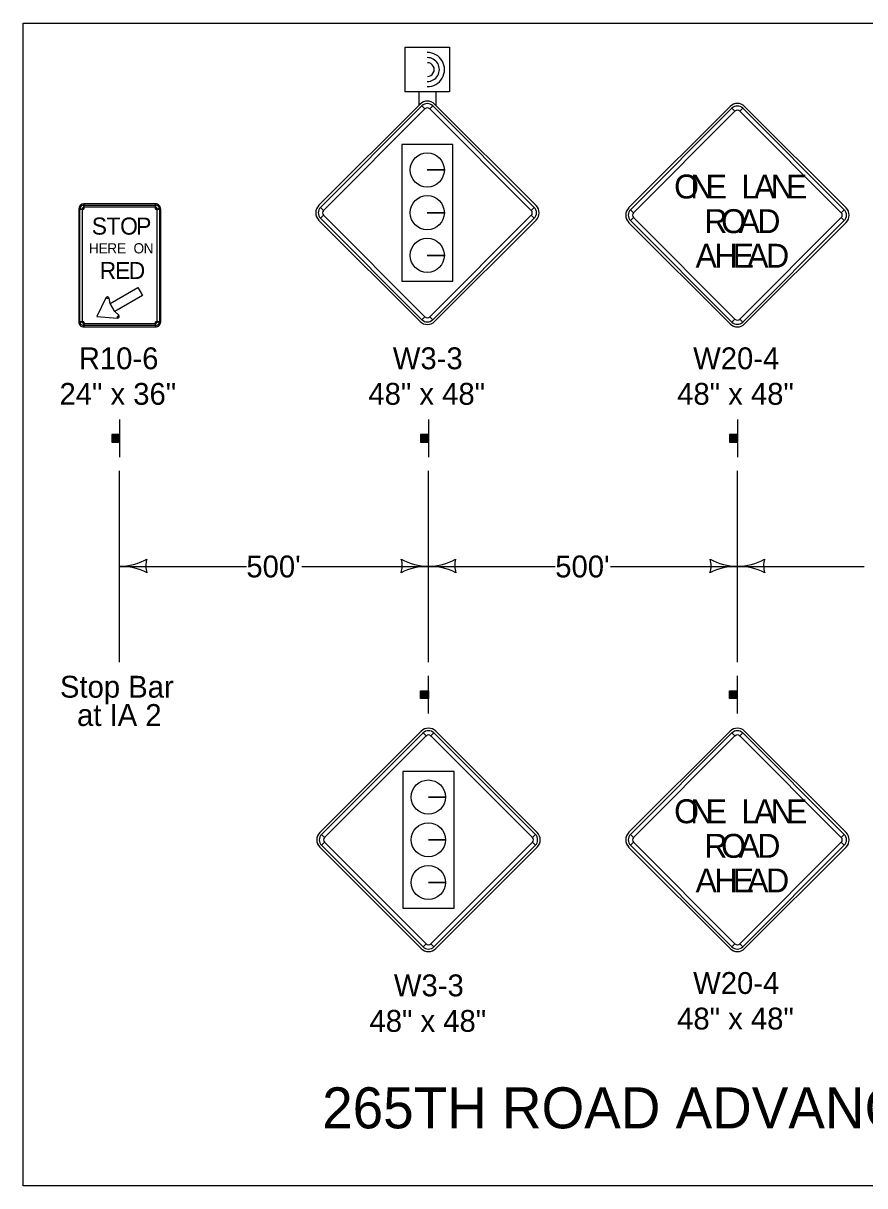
# Model space of a CAD drawing. Extents: x -2134934 to -2119606, y -2139046 to -2137036.
# Drawn here: x -2120727 to -2120111, y -2137987 to -2137136 of the extents above; entities that cross this region are included whole.
import ezdxf

# ---------------------------------------------------------------- set-up
doc = ezdxf.new("R2010")
doc.units = 0
doc.layers.add('dsnStdLabel', color=7, linetype='Continuous')
doc.layers.add('Level 2', color=7, linetype='Continuous')

msp = doc.modelspace()

# ---------------------------------------------------------------- linework, layer by layer
at = {"layer": 'dsnStdLabel'}
for p, q in [((-2120436.56, -2137195.1), (-2120510.81, -2137269.35)), ((-2120435.23, -2137196.43), (-2120433.02, -2137198.64)), ((-2120429.49, -2137198.64), (-2120427.28, -2137196.43)), ((-2120351.71, -2137269.35), (-2120425.95, -2137195.1)), ((-2120209.72, -2137196.82), (-2120283.97, -2137271.07)), ((-2120208.4, -2137198.15), (-2120206.19, -2137200.36)), ((-2120202.65, -2137200.36), (-2120200.44, -2137198.15)), ((-2120124.87, -2137271.07), (-2120199.12, -2137196.82)), ((-2120418.85, -2137243.32), (-2120431.35, -2137243.32)), ((-2120431.35, -2137243.32), (-2120418.85, -2137243.32)), ((-2120682.65, -2137271.87), (-2120682.65, -2137268.12)), ((-2120682.65, -2137270.62), (-2120682.65, -2137269.05)), ((-2120630.15, -2137268.12), (-2120630.15, -2137271.87)), ((-2120630.15, -2137269.05), (-2120630.15, -2137270.62)), ((-2120686.4, -2137271.87), (-2120682.65, -2137271.87)), ((-2120685.46, -2137271.87), (-2120683.9, -2137271.87)), ((-2120630.15, -2137271.87), (-2120626.4, -2137271.87)), ((-2120628.9, -2137271.87), (-2120627.33, -2137271.87)), ((-2120507.27, -2137272.88), (-2120509.48, -2137270.67)), ((-2120509.48, -2137278.63), (-2120507.27, -2137276.42)), ((-2120418.85, -2137274.57), (-2120431.35, -2137274.57)), ((-2120431.35, -2137274.57), (-2120418.85, -2137274.57)), ((-2120353.03, -2137270.67), (-2120355.24, -2137272.88)), ((-2120355.24, -2137276.42), (-2120353.03, -2137278.63)), ((-2120280.43, -2137274.6), (-2120282.64, -2137272.39)), ((-2120282.64, -2137280.35), (-2120280.43, -2137278.14)), ((-2120126.2, -2137272.39), (-2120128.4, -2137274.6)), ((-2120128.4, -2137278.14), (-2120126.2, -2137280.35)), ((-2120510.81, -2137279.95), (-2120436.56, -2137354.2)), ((-2120425.95, -2137354.2), (-2120351.71, -2137279.95)), ((-2120283.97, -2137281.67), (-2120209.72, -2137355.92)), ((-2120199.12, -2137355.92), (-2120124.87, -2137281.67)), ((-2120418.85, -2137305.82), (-2120431.35, -2137305.82)), ((-2120431.35, -2137305.82), (-2120418.85, -2137305.82)), ((-2120666.54, -2137336.85), (-2120665.43, -2137337.43)), ((-2120665.43, -2137337.43), (-2120664.21, -2137337.16)), ((-2120682.65, -2137354.37), (-2120686.4, -2137354.37)), ((-2120683.9, -2137354.37), (-2120685.46, -2137354.37)), ((-2120682.65, -2137358.12), (-2120682.65, -2137354.37)), ((-2120657.93, -2137350.42), (-2120657.98, -2137351.67)), ((-2120657.08, -2137349.5), (-2120657.93, -2137350.42)), ((-2120626.4, -2137354.37), (-2120630.15, -2137354.37)), ((-2120630.15, -2137354.37), (-2120630.15, -2137358.12)), ((-2120627.33, -2137354.37), (-2120628.9, -2137354.37)), ((-2120433.02, -2137350.66), (-2120435.23, -2137352.87)), ((-2120427.28, -2137352.87), (-2120429.49, -2137350.66)), ((-2120206.19, -2137352.38), (-2120208.4, -2137354.59)), ((-2120200.44, -2137354.59), (-2120202.65, -2137352.38)), ((-2120682.65, -2137357.18), (-2120682.65, -2137355.62)), ((-2120630.15, -2137355.62), (-2120630.15, -2137357.18)), ((-2120435.76, -2137653.96), (-2120510, -2137728.2)), ((-2120434.43, -2137655.28), (-2120432.22, -2137657.49)), ((-2120428.69, -2137657.49), (-2120426.48, -2137655.28)), ((-2120350.9, -2137728.2), (-2120425.15, -2137653.96)), ((-2120209.72, -2137653.96), (-2120283.97, -2137728.2)), ((-2120208.4, -2137655.28), (-2120206.19, -2137657.49)), ((-2120202.65, -2137657.49), (-2120200.44, -2137655.28)), ((-2120124.87, -2137728.2), (-2120199.12, -2137653.96)), ((-2120418.05, -2137702.18), (-2120430.55, -2137702.18)), ((-2120430.55, -2137702.18), (-2120418.05, -2137702.18)), ((-2120506.47, -2137731.74), (-2120508.68, -2137729.53)), ((-2120508.68, -2137737.48), (-2120506.47, -2137735.27)), ((-2120418.05, -2137733.43), (-2120430.55, -2137733.43)), ((-2120430.55, -2137733.43), (-2120418.05, -2137733.43)), ((-2120352.23, -2137729.53), (-2120354.44, -2137731.74)), ((-2120354.44, -2137735.27), (-2120352.23, -2137737.48)), ((-2120280.43, -2137731.74), (-2120282.64, -2137729.53)), ((-2120282.64, -2137737.49), (-2120280.43, -2137735.28)), ((-2120126.2, -2137729.53), (-2120128.4, -2137731.74)), ((-2120128.4, -2137735.28), (-2120126.2, -2137737.49)), ((-2120510, -2137738.81), (-2120435.76, -2137813.06)), ((-2120425.15, -2137813.06), (-2120350.9, -2137738.81)), ((-2120283.97, -2137738.81), (-2120209.72, -2137813.06)), ((-2120199.12, -2137813.06), (-2120124.87, -2137738.81)), ((-2120418.05, -2137764.68), (-2120430.55, -2137764.68)), ((-2120430.55, -2137764.68), (-2120418.05, -2137764.68)), ((-2120432.22, -2137809.52), (-2120434.43, -2137811.73)), ((-2120426.48, -2137811.73), (-2120428.69, -2137809.52)), ((-2120206.19, -2137809.52), (-2120208.4, -2137811.73)), ((-2120200.44, -2137811.73), (-2120202.65, -2137809.52))]:
    msp.add_line(p, q, dxfattribs=at)
for points in [[(-2120726.97, -2137135.95), (-2119605.73, -2137135.95), (-2119605.73, -2137986.59), (-2120726.97, -2137986.59)], [(-2120435.23, -2137196.43), (-2120509.48, -2137270.67), (-2120507.27, -2137272.88), (-2120433.02, -2137198.64), (-2120435.23, -2137196.43)], [(-2120353.03, -2137270.67), (-2120427.28, -2137196.43), (-2120429.49, -2137198.64), (-2120355.24, -2137272.88), (-2120353.03, -2137270.67)], [(-2120208.4, -2137198.15), (-2120282.64, -2137272.39), (-2120280.43, -2137274.6), (-2120206.19, -2137200.36), (-2120208.4, -2137198.15)], [(-2120126.2, -2137272.39), (-2120200.44, -2137198.15), (-2120202.65, -2137200.36), (-2120128.4, -2137274.6), (-2120126.2, -2137272.39)], [(-2120412.53, -2137224.71), (-2120449.99, -2137224.71), (-2120449.99, -2137324.6), (-2120412.53, -2137324.6), (-2120412.53, -2137224.71)], [(-2120682.65, -2137358.12), (-2120630.15, -2137358.12), (-2120630.15, -2137354.37), (-2120626.4, -2137354.37), (-2120626.4, -2137271.87), (-2120630.15, -2137271.87), (-2120630.15, -2137268.12), (-2120682.65, -2137268.12), (-2120682.65, -2137271.87), (-2120686.4, -2137271.87), (-2120686.4, -2137354.37), (-2120682.65, -2137354.37), (-2120682.65, -2137358.12)], [(-2120630.15, -2137270.62), (-2120682.65, -2137270.62), (-2120682.65, -2137269.05), (-2120630.15, -2137269.05), (-2120630.15, -2137270.62)], [(-2120683.9, -2137271.87), (-2120683.9, -2137354.37), (-2120685.46, -2137354.37), (-2120685.46, -2137271.87), (-2120683.9, -2137271.87)], [(-2120628.9, -2137354.37), (-2120628.9, -2137271.87), (-2120627.33, -2137271.87), (-2120627.33, -2137354.37), (-2120628.9, -2137354.37)], [(-2120509.48, -2137278.63), (-2120435.23, -2137352.87), (-2120433.02, -2137350.66), (-2120507.27, -2137276.42), (-2120509.48, -2137278.63)], [(-2120427.28, -2137352.87), (-2120353.03, -2137278.63), (-2120355.24, -2137276.42), (-2120429.49, -2137350.66), (-2120427.28, -2137352.87)], [(-2120282.64, -2137280.35), (-2120208.4, -2137354.59), (-2120206.19, -2137352.38), (-2120280.43, -2137278.14), (-2120282.64, -2137280.35)], [(-2120200.44, -2137354.59), (-2120126.2, -2137280.35), (-2120128.4, -2137278.14), (-2120202.65, -2137352.38), (-2120200.44, -2137354.59)], [(-2120643.02, -2137329.37), (-2120639.74, -2137335.05), (-2120660.05, -2137346.77), (-2120663.33, -2137341.09), (-2120643.02, -2137329.37)], [(-2120673.05, -2137350.49), (-2120657.98, -2137351.67), (-2120657.93, -2137350.42), (-2120657.08, -2137349.5), (-2120660.05, -2137346.77), (-2120663.33, -2137341.09), (-2120664.21, -2137337.16), (-2120665.43, -2137337.43), (-2120666.54, -2137336.85), (-2120673.05, -2137350.49)], [(-2120682.65, -2137355.62), (-2120630.15, -2137355.62), (-2120630.15, -2137357.18), (-2120682.65, -2137357.18), (-2120682.65, -2137355.62)], [(-2120434.43, -2137655.28), (-2120508.68, -2137729.53), (-2120506.47, -2137731.74), (-2120432.22, -2137657.49), (-2120434.43, -2137655.28)], [(-2120352.23, -2137729.53), (-2120426.48, -2137655.28), (-2120428.69, -2137657.49), (-2120354.44, -2137731.74), (-2120352.23, -2137729.53)], [(-2120208.4, -2137655.28), (-2120282.64, -2137729.53), (-2120280.43, -2137731.74), (-2120206.19, -2137657.49), (-2120208.4, -2137655.28)], [(-2120126.2, -2137729.53), (-2120200.44, -2137655.28), (-2120202.65, -2137657.49), (-2120128.4, -2137731.74), (-2120126.2, -2137729.53)], [(-2120411.72, -2137683.56), (-2120449.19, -2137683.56), (-2120449.19, -2137783.45), (-2120411.72, -2137783.45), (-2120411.72, -2137683.56)], [(-2120508.68, -2137737.48), (-2120434.43, -2137811.73), (-2120432.22, -2137809.52), (-2120506.47, -2137735.27), (-2120508.68, -2137737.48)], [(-2120426.48, -2137811.73), (-2120352.23, -2137737.48), (-2120354.44, -2137735.27), (-2120428.69, -2137809.52), (-2120426.48, -2137811.73)], [(-2120282.64, -2137737.49), (-2120208.4, -2137811.73), (-2120206.19, -2137809.52), (-2120280.43, -2137735.28), (-2120282.64, -2137737.49)], [(-2120200.44, -2137811.73), (-2120126.2, -2137737.49), (-2120128.4, -2137735.28), (-2120202.65, -2137809.52), (-2120200.44, -2137811.73)]]:
    msp.add_lwpolyline(points, close=True, dxfattribs=at)
for centre in [(-2120431.35, -2137243.32), (-2120431.35, -2137274.57), (-2120431.35, -2137305.82), (-2120430.55, -2137702.18), (-2120430.55, -2137733.43), (-2120430.55, -2137764.68)]:
    msp.add_circle(centre, 12.5, dxfattribs=at)
for centre, radius, start, end in [((-2120431.26, -2137200.41), 7.5, 44.99999, 134.99974), ((-2120431.26, -2137200.41), 5.62, 44.99999, 134.99974), ((-2120431.26, -2137200.41), 2.5, 44.99999, 134.99974), ((-2120204.42, -2137202.12), 7.5, 44.99999, 134.99974), ((-2120204.42, -2137202.12), 5.62, 44.99999, 134.99974), ((-2120204.42, -2137202.12), 2.5, 44.99999, 134.99974), ((-2120682.65, -2137271.87), 3.75, 90.00021, 179.99985), ((-2120682.65, -2137271.87), 2.81, 90.00021, 179.99985), ((-2120630.15, -2137271.87), 3.75, 0, 90.00021), ((-2120630.15, -2137271.87), 2.81, 0, 90.00021), ((-2120505.5, -2137274.65), 7.5, 134.99974, 224.99995), ((-2120357.01, -2137274.65), 7.5, 315.00016, 44.9998), ((-2120682.65, -2137271.87), 1.25, 90.00021, 179.99985), ((-2120630.15, -2137271.87), 1.25, 0, 90.00021), ((-2120505.5, -2137274.65), 5.62, 134.99974, 224.99995), ((-2120505.5, -2137274.65), 2.5, 134.99974, 224.99995), ((-2120357.01, -2137274.65), 2.5, 315.00016, 44.9998), ((-2120357.01, -2137274.65), 5.62, 315.00016, 44.9998), ((-2120278.66, -2137276.37), 7.5, 134.99974, 224.99995), ((-2120278.66, -2137276.37), 5.62, 134.99974, 224.99995), ((-2120278.66, -2137276.37), 2.5, 134.99974, 224.99995), ((-2120130.17, -2137276.37), 2.5, 315.00016, 44.9998), ((-2120130.17, -2137276.37), 5.62, 315.00016, 44.9998), ((-2120130.17, -2137276.37), 7.5, 315.00016, 44.9998), ((-2120665.43, -2137337.43), 1.25, 12.62232, 152.27557), ((-2120682.65, -2137354.37), 3.75, 179.99985, 270.00006), ((-2120682.65, -2137354.37), 2.81, 179.99985, 270.00006), ((-2120682.65, -2137354.37), 1.25, 179.99985, 270.00006), ((-2120657.93, -2137350.42), 1.25, 267.72427, 47.37758), ((-2120630.15, -2137354.37), 3.75, 270.00006, 0.00027), ((-2120630.15, -2137354.37), 2.81, 270.00006, 0.00027), ((-2120630.15, -2137354.37), 1.25, 270.00006, 0.00027), ((-2120431.26, -2137348.9), 7.5, 224.99995, 315.00016), ((-2120431.26, -2137348.9), 5.62, 224.99995, 315.00016), ((-2120431.26, -2137348.9), 2.5, 224.99995, 315.00016), ((-2120204.42, -2137350.62), 5.62, 224.99995, 315.00016), ((-2120204.42, -2137350.62), 2.5, 224.99995, 315.00016), ((-2120204.42, -2137350.62), 7.5, 224.99995, 315.00016), ((-2120430.45, -2137659.26), 7.5, 44.99999, 134.99974), ((-2120204.42, -2137659.26), 7.5, 44.99999, 134.99974), ((-2120430.45, -2137659.26), 5.62, 44.99999, 134.99974), ((-2120430.45, -2137659.26), 2.5, 44.99999, 134.99974), ((-2120204.42, -2137659.26), 5.62, 44.99999, 134.99974), ((-2120204.42, -2137659.26), 2.5, 44.99999, 134.99974), ((-2120504.7, -2137733.51), 7.5, 134.99974, 224.99995), ((-2120356.21, -2137733.51), 7.5, 315.00016, 44.9998), ((-2120278.66, -2137733.51), 7.5, 134.99974, 224.99995), ((-2120130.17, -2137733.51), 7.5, 315.00016, 44.9998), ((-2120504.7, -2137733.51), 5.62, 134.99974, 224.99995), ((-2120504.7, -2137733.51), 2.5, 134.99974, 224.99995), ((-2120356.21, -2137733.51), 2.5, 315.00016, 44.9998), ((-2120356.21, -2137733.51), 5.62, 315.00016, 44.9998), ((-2120278.66, -2137733.51), 5.62, 134.99974, 224.99995), ((-2120278.66, -2137733.51), 2.5, 134.99974, 224.99995), ((-2120130.17, -2137733.51), 2.5, 315.00016, 44.9998), ((-2120130.17, -2137733.51), 5.62, 315.00016, 44.9998), ((-2120430.45, -2137807.75), 7.5, 224.99995, 315.00016), ((-2120430.45, -2137807.75), 5.62, 224.99995, 315.00016), ((-2120430.45, -2137807.75), 2.5, 224.99995, 315.00016), ((-2120204.42, -2137807.75), 7.5, 224.99995, 315.00016), ((-2120204.42, -2137807.75), 5.62, 224.99995, 315.00016), ((-2120204.42, -2137807.75), 2.5, 224.99995, 315.00016)]:
    msp.add_arc(centre, radius, start, end, dxfattribs=at)
at = {"layer": 'Level 2'}
for p, q in [((-2120437.49, -2137186.06), (-2120437.49, -2137196.06)), ((-2120424.99, -2137186.06), (-2120424.99, -2137196.06)), ((-2120656.49, -2137425.94), (-2120656.49, -2137453.44)), ((-2120430.45, -2137425.94), (-2120430.45, -2137453.44)), ((-2120204.42, -2137425.94), (-2120204.42, -2137453.44)), ((-2120661.82, -2137436.8), (-2120661.82, -2137442.39)), ((-2120661.5, -2137442.39), (-2120661.5, -2137436.8)), ((-2120661.27, -2137436.8), (-2120661.27, -2137442.39)), ((-2120660.95, -2137442.39), (-2120660.95, -2137436.8)), ((-2120660.73, -2137436.8), (-2120660.75, -2137442.39)), ((-2120660.32, -2137442.39), (-2120660.3, -2137436.8)), ((-2120660.09, -2137436.8), (-2120660.09, -2137442.39)), ((-2120659.66, -2137442.39), (-2120659.66, -2137436.8)), ((-2120659.29, -2137436.8), (-2120659.29, -2137442.39)), ((-2120658.97, -2137442.39), (-2120658.95, -2137436.8)), ((-2120658.74, -2137436.8), (-2120658.74, -2137442.39)), ((-2120658.48, -2137442.39), (-2120658.48, -2137436.8)), ((-2120658.14, -2137436.8), (-2120658.14, -2137442.39)), ((-2120657.94, -2137442.39), (-2120657.94, -2137436.8)), ((-2120657.71, -2137436.8), (-2120657.71, -2137442.39)), ((-2120657.45, -2137442.39), (-2120657.45, -2137436.8)), ((-2120657.19, -2137436.8), (-2120657.19, -2137442.39)), ((-2120656.9, -2137442.39), (-2120656.9, -2137436.8)), ((-2120435.78, -2137436.8), (-2120435.78, -2137442.39)), ((-2120435.46, -2137442.39), (-2120435.46, -2137436.8)), ((-2120435.24, -2137436.8), (-2120435.24, -2137442.39)), ((-2120434.92, -2137442.39), (-2120434.92, -2137436.8)), ((-2120434.69, -2137436.8), (-2120434.71, -2137442.39)), ((-2120434.28, -2137442.39), (-2120434.26, -2137436.8)), ((-2120434.06, -2137436.8), (-2120434.06, -2137442.39)), ((-2120433.62, -2137442.39), (-2120433.62, -2137436.8)), ((-2120433.25, -2137436.8), (-2120433.25, -2137442.39)), ((-2120432.93, -2137442.39), (-2120432.91, -2137436.8)), ((-2120432.71, -2137436.8), (-2120432.71, -2137442.39)), ((-2120432.44, -2137442.39), (-2120432.44, -2137436.8)), ((-2120432.11, -2137436.8), (-2120432.11, -2137442.39)), ((-2120431.9, -2137442.39), (-2120431.9, -2137436.8)), ((-2120431.67, -2137436.8), (-2120431.67, -2137442.39)), ((-2120431.41, -2137442.39), (-2120431.41, -2137436.8)), ((-2120431.15, -2137436.8), (-2120431.15, -2137442.39)), ((-2120430.87, -2137442.39), (-2120430.87, -2137436.8)), ((-2120209.74, -2137436.8), (-2120209.74, -2137442.39)), ((-2120209.43, -2137442.39), (-2120209.43, -2137436.8)), ((-2120209.2, -2137436.8), (-2120209.2, -2137442.39)), ((-2120208.88, -2137442.39), (-2120208.88, -2137436.8)), ((-2120208.66, -2137436.8), (-2120208.68, -2137442.39)), ((-2120208.24, -2137442.39), (-2120208.23, -2137436.8)), ((-2120208.02, -2137436.8), (-2120208.02, -2137442.39)), ((-2120207.59, -2137442.39), (-2120207.59, -2137436.8)), ((-2120207.21, -2137436.8), (-2120207.21, -2137442.39)), ((-2120206.89, -2137442.39), (-2120206.88, -2137436.8)), ((-2120206.67, -2137436.8), (-2120206.67, -2137442.39)), ((-2120206.41, -2137442.39), (-2120206.41, -2137436.8)), ((-2120206.07, -2137436.8), (-2120206.07, -2137442.39)), ((-2120205.86, -2137442.39), (-2120205.86, -2137436.8)), ((-2120205.64, -2137436.8), (-2120205.64, -2137442.39)), ((-2120205.38, -2137442.39), (-2120205.38, -2137436.8)), ((-2120205.11, -2137436.8), (-2120205.11, -2137442.39)), ((-2120204.83, -2137442.39), (-2120204.83, -2137436.8)), ((-2120656.49, -2137603.44), (-2120656.49, -2137463.44)), ((-2120430.45, -2137603.44), (-2120430.45, -2137463.44)), ((-2120204.42, -2137603.44), (-2120204.42, -2137463.44)), ((-2120656.49, -2137533.44), (-2120563.72, -2137533.44)), ((-2120523.22, -2137533.44), (-2120430.45, -2137533.44)), ((-2120430.45, -2137533.44), (-2120337.69, -2137533.44)), ((-2120297.19, -2137533.44), (-2120204.42, -2137533.44)), ((-2120204.42, -2137533.44), (-2120111.65, -2137533.44)), ((-2120430.45, -2137640.94), (-2120430.45, -2137613.44)), ((-2120204.42, -2137640.94), (-2120204.42, -2137613.44)), ((-2120435.78, -2137630.08), (-2120435.78, -2137624.49)), ((-2120435.46, -2137624.49), (-2120435.46, -2137630.08)), ((-2120435.24, -2137630.08), (-2120435.24, -2137624.49)), ((-2120434.92, -2137624.49), (-2120434.92, -2137630.08)), ((-2120434.69, -2137630.08), (-2120434.71, -2137624.49)), ((-2120434.28, -2137624.49), (-2120434.26, -2137630.08)), ((-2120434.06, -2137630.08), (-2120434.06, -2137624.49)), ((-2120433.62, -2137624.49), (-2120433.62, -2137630.08)), ((-2120433.25, -2137630.08), (-2120433.25, -2137624.49)), ((-2120432.93, -2137624.49), (-2120432.91, -2137630.08)), ((-2120432.71, -2137630.08), (-2120432.71, -2137624.49)), ((-2120432.44, -2137624.49), (-2120432.44, -2137630.08)), ((-2120432.11, -2137630.08), (-2120432.11, -2137624.49)), ((-2120431.9, -2137624.49), (-2120431.9, -2137630.08)), ((-2120431.67, -2137630.08), (-2120431.67, -2137624.49)), ((-2120431.41, -2137624.49), (-2120431.41, -2137630.08)), ((-2120431.15, -2137630.08), (-2120431.15, -2137624.49)), ((-2120430.87, -2137624.49), (-2120430.87, -2137630.08)), ((-2120209.74, -2137630.08), (-2120209.74, -2137624.49)), ((-2120209.43, -2137624.49), (-2120209.43, -2137630.08)), ((-2120209.2, -2137630.08), (-2120209.2, -2137624.49)), ((-2120208.88, -2137624.49), (-2120208.88, -2137630.08)), ((-2120208.66, -2137630.08), (-2120208.68, -2137624.49)), ((-2120208.24, -2137624.49), (-2120208.23, -2137630.08)), ((-2120208.02, -2137630.08), (-2120208.02, -2137624.49)), ((-2120207.59, -2137624.49), (-2120207.59, -2137630.08)), ((-2120207.21, -2137630.08), (-2120207.21, -2137624.49)), ((-2120206.89, -2137624.49), (-2120206.88, -2137630.08)), ((-2120206.67, -2137630.08), (-2120206.67, -2137624.49)), ((-2120206.41, -2137624.49), (-2120206.41, -2137630.08)), ((-2120206.07, -2137630.08), (-2120206.07, -2137624.49)), ((-2120205.86, -2137624.49), (-2120205.86, -2137630.08)), ((-2120205.64, -2137630.08), (-2120205.64, -2137624.49)), ((-2120205.38, -2137624.49), (-2120205.38, -2137630.08)), ((-2120205.11, -2137630.08), (-2120205.11, -2137624.49)), ((-2120204.83, -2137624.49), (-2120204.83, -2137630.08))]:
    msp.add_line(p, q, dxfattribs=at)
for points in [[(-2120447.49, -2137186.06), (-2120447.49, -2137153.56), (-2120414.99, -2137153.56), (-2120414.99, -2137186.06)], [(-2120656.59, -2137442.39), (-2120656.59, -2137436.76), (-2120662.21, -2137436.76), (-2120662.21, -2137442.39)], [(-2120430.55, -2137442.39), (-2120430.55, -2137436.76), (-2120436.17, -2137436.76), (-2120436.17, -2137442.39)], [(-2120204.51, -2137442.39), (-2120204.51, -2137436.76), (-2120210.14, -2137436.76), (-2120210.14, -2137442.39)], [(-2120430.55, -2137624.49), (-2120430.55, -2137630.12), (-2120436.17, -2137630.12), (-2120436.17, -2137624.49)], [(-2120204.51, -2137624.49), (-2120204.51, -2137630.12), (-2120210.14, -2137630.12), (-2120210.14, -2137624.49)]]:
    msp.add_lwpolyline(points, close=True, dxfattribs=at)
for centre, radius, start, end in [((-2120431.23, -2137169.83), 12.5, 269.40414, 90.54446), ((-2120431.23, -2137169.83), 12.5, 269.40414, 90.54446), ((-2120431.23, -2137169.83), 8.75, 269.40414, 90.54446), ((-2120431.23, -2137169.83), 5, 269.40414, 90.54446), ((-2120657.25, -2137490.95), 42.5, 271.0176, 299.07249), ((-2120655.76, -2137575.93), 42.5, 62.92751, 90.9824), ((-2120620.87, -2137532.82), 16.42, 163.26665, 198.73335), ((-2120466.07, -2137532.82), 16.42, 341.26665, 16.73335), ((-2120431.18, -2137575.93), 42.5, 89.0176, 117.07249), ((-2120429.7, -2137490.95), 42.5, 240.92751, 268.9824), ((-2120431.21, -2137490.95), 42.5, 271.0176, 299.07249), ((-2120429.73, -2137575.93), 42.5, 62.92751, 90.9824), ((-2120394.84, -2137532.82), 16.42, 163.26665, 198.73335), ((-2120240.04, -2137532.82), 16.42, 341.26665, 16.73335), ((-2120205.15, -2137575.93), 42.5, 89.0176, 117.07249), ((-2120203.66, -2137490.95), 42.5, 240.92751, 268.9824), ((-2120205.17, -2137490.95), 42.5, 271.0176, 299.07249), ((-2120203.69, -2137575.93), 42.5, 62.92751, 90.9824), ((-2120168.8, -2137532.82), 16.42, 163.26665, 198.73335)]:
    msp.add_arc(centre, radius, start, end, dxfattribs=at)

# ---------------------------------------------------------------- texts
at = {"layer": 'dsnStdLabel'}
for s, height, p in [('O', 17.5, (-2120250.7, -2137264.18)), ('N', 17.5, (-2120238.93, -2137264.18)), ('E', 17.5, (-2120227.7, -2137264.18)), ('L', 17.5, (-2120201.45, -2137264.18)), ('A', 17.5, (-2120192.25, -2137264.18)), ('N', 17.5, (-2120179.99, -2137264.18)), ('E', 17.5, (-2120168.76, -2137264.18)), ('S', 12.5, (-2120676.84, -2137290.62)), ('T', 12.5, (-2120666.08, -2137290.62)), ('O', 12.5, (-2120656.09, -2137290.62)), ('P', 12.5, (-2120644.35, -2137290.62)), ('R', 17.5, (-2120228.6, -2137289.5)), ('O', 17.5, (-2120216.31, -2137289.5)), ('A', 17.5, (-2120203.47, -2137289.5)), ('D', 17.5, (-2120189.81, -2137289.5)), ('H', 7.5, (-2120678.92, -2137304.37)), ('E', 7.5, (-2120671.77, -2137304.37)), ('R', 7.5, (-2120665.51, -2137304.37)), ('E', 7.5, (-2120658.36, -2137304.37)), ('O', 7.5, (-2120646.29, -2137304.37)), ('N', 7.5, (-2120638.91, -2137304.37)), ('A', 17.5, (-2120235.03, -2137314.81)), ('H', 17.5, (-2120221.17, -2137314.81)), ('E', 17.5, (-2120207.95, -2137314.81)), ('A', 17.5, (-2120197.24, -2137314.81)), ('D', 17.5, (-2120183.37, -2137314.81)), ('R', 12.5, (-2120671.08, -2137323.12)), ('E', 12.5, (-2120659.75, -2137323.12)), ('D', 12.5, (-2120649.79, -2137323.12)), ('R10-6', 16, (-2120686.32, -2137389.12)), ('W3-3', 16, (-2120456.55, -2137389.12)), ('W20-4', 16, (-2120236.78, -2137389.12)), ('24" x 36"', 16, (-2120700.46, -2137415.12)), ('48" x 48"', 16, (-2120474.43, -2137415.12)), ('48" x 48"', 16, (-2120248.49, -2137415.12)), ('O', 17.5, (-2120250.7, -2137721.32)), ('N', 17.5, (-2120238.93, -2137721.32)), ('E', 17.5, (-2120227.7, -2137721.32)), ('L', 17.5, (-2120201.45, -2137721.32)), ('A', 17.5, (-2120192.25, -2137721.32)), ('N', 17.5, (-2120179.99, -2137721.32)), ('E', 17.5, (-2120168.76, -2137721.32)), ('R', 17.5, (-2120228.6, -2137746.63)), ('O', 17.5, (-2120216.31, -2137746.63)), ('A', 17.5, (-2120203.47, -2137746.63)), ('D', 17.5, (-2120189.81, -2137746.63)), ('A', 17.5, (-2120235.03, -2137771.95)), ('H', 17.5, (-2120221.17, -2137771.95)), ('E', 17.5, (-2120207.95, -2137771.95)), ('A', 17.5, (-2120197.24, -2137771.95)), ('D', 17.5, (-2120183.37, -2137771.95)), ('W20-4', 16, (-2120236.78, -2137846.25)), ('W3-3', 16, (-2120455.75, -2137847.97)), ('48" x 48"', 16, (-2120248.49, -2137872.25)), ('48" x 48"', 16, (-2120473.62, -2137873.97)), ('265TH ROAD ADVANCED SIGNING', 30, (-2120508.22, -2137944.59))]:
    msp.add_text(s, height=height, dxfattribs=at).set_placement(p)
at = {"layer": 'Level 2'}
for s, p in [("500'", (-2120563.72, -2137541.44)), ("500'", (-2120337.69, -2137541.44)), ('Stop Bar', (-2120700.12, -2137629.44)), ('at IA 2', (-2120687.58, -2137650.15))]:
    msp.add_text(s, height=16, dxfattribs=at).set_placement(p)

doc.saveas('drawing.dxf')
